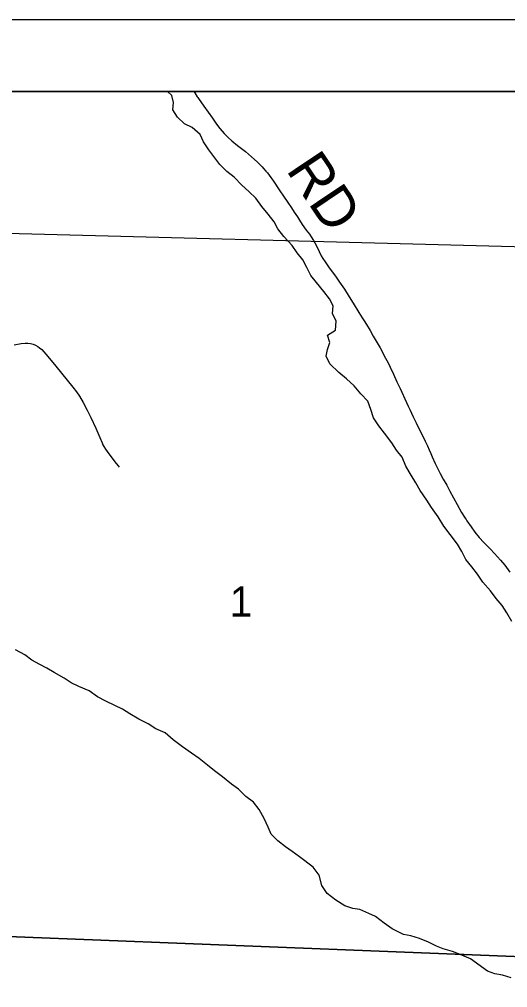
# Model space of a CAD drawing. Extents: x 0 to 34, y 0 to 22.
# Drawn here: x 26.316 to 26.994, y 19.658 to 21 of the extents above; entities that cross this region are included whole.
import ezdxf

# ---------------------------------------------------------------- set-up
doc = ezdxf.new("R2010")
doc.units = 0
for name, color, linetype in [('GM_X_Corporation', 7, 'Continuous'), ('GM_X_Minor_River', 7, 'Continuous'), ('GM_X_Section_Text', 7, 'Continuous'), ('GM_X_Township_Road', 7, 'Continuous'), ('GM_X_Township_Road_Text', 7, 'Continuous'), ('SH_Data', 7, 'Continuous')]:
    doc.layers.add(name, color=color, linetype=linetype)

msp = doc.modelspace()

# ---------------------------------------------------------------- linework, layer by layer
at = {"layer": 'GM_X_Corporation'}
for points in [[(30.3167, 20.9), (23.5167, 20.9), (23.5167, 14.7114), (24.6586, 14.6808), (24.6805, 14.6799), (26.0522, 14.6391), (26.4447, 14.6283), (26.4468, 14.6272), (26.4498, 14.6263), (26.4544, 14.6257), (26.5226, 14.6248), (26.5325, 14.6248), (26.5616, 14.6241), (26.5684, 14.624), (26.5727, 14.624), (26.5813, 14.6239), (26.5991, 14.6234), (26.6128, 14.6229), (26.6208, 14.6225), (26.6337, 14.622), (26.643, 14.6216), (26.6535, 14.621), (27.01, 14.6164)], [(30.3167, 20.9), (25.1014, 20.9), (25.0988, 20.7425), (25.0847, 19.8351), (25.0701, 18.7696), (25.0668, 18.5474), (25.0619, 17.7438), (25.4012, 17.7333), (26.0747, 17.7146), (26.0759, 17.6934), (26.0745, 17.4524), (26.0677, 16.948), (26.0646, 16.863), (26.0683, 16.6823), (26.3378, 16.673), (27.0694, 16.6556)]]:
    msp.add_lwpolyline(points, dxfattribs=at)
for points in [[(27.1148, 20.9), (26.1019, 20.9), (26.0969, 20.7089), (26.1216, 20.708), (27.1086, 20.6823)], [(26.1216, 20.708), (27.1086, 20.6823), (27.14, 20.6818), (27.1321, 19.6957), (26.1009, 19.7362)], [(27.1321, 19.6957), (27.1305, 19.6616), (27.1072, 18.6988), (26.0916, 18.7368), (26.1009, 19.7362)]]:
    msp.add_lwpolyline(points, close=True, dxfattribs=at)
at = {"layer": 'GM_X_Minor_River'}
for points in [[(26.9998, 20.1654), (26.9929, 20.1774), (26.986, 20.1872), (26.978, 20.197), (26.97, 20.2079), (26.9593, 20.2199), (26.952, 20.2308), (26.9443, 20.241), (26.9359, 20.2511), (26.9302, 20.2624), (26.9244, 20.2726), (26.9141, 20.2858), (26.9053, 20.2974), (26.8976, 20.3102), (26.888, 20.3234), (26.8819, 20.3332), (26.8723, 20.3467), (26.8662, 20.3576), (26.86, 20.3682), (26.8524, 20.3806), (26.8474, 20.3931), (26.8397, 20.4028), (26.8332, 20.413), (26.8229, 20.4265), (26.8152, 20.4363), (26.8079, 20.4476), (26.804, 20.4593), (26.7998, 20.4706), (26.7899, 20.4807), (26.7807, 20.492), (26.77, 20.5014), (26.7594, 20.5104), (26.7472, 20.5224), (26.7422, 20.5329), (26.744, 20.5424), (26.7473, 20.5519), (26.7438, 20.5621), (26.7551, 20.5691), (26.7557, 20.5816), (26.7507, 20.5921), (26.7517, 20.6028), (26.7467, 20.6126), (26.7387, 20.6227), (26.7288, 20.6351), (26.7207, 20.6449), (26.715, 20.6562), (26.7096, 20.6664), (26.7016, 20.6761), (26.6947, 20.6867), (26.6832, 20.6991), (26.6748, 20.7096), (26.6698, 20.7194), (26.6614, 20.7299), (26.6526, 20.7404), (26.6442, 20.7521), (26.6347, 20.7615), (26.6248, 20.7701), (26.6144, 20.7813), (26.6042, 20.7892), (26.5946, 20.799), (26.579, 20.8193), (26.5717, 20.8302), (26.567, 20.8404), (26.556, 20.8501), (26.5454, 20.8553), (26.5358, 20.8643), (26.5293, 20.8748), (26.53, 20.8847), (26.528, 20.8945), (26.5218, 20.9)], [(26.7048, 19.8387), (26.6949, 19.8461), (26.6854, 19.8529), (26.6751, 19.8611), (26.6656, 19.8701), (26.6614, 19.8799), (26.656, 19.8919), (26.6491, 19.9044), (26.641, 19.9149), (26.6307, 19.9224), (26.6205, 19.9329), (26.6106, 19.9396), (26.5984, 19.9497), (26.5873, 19.9583), (26.5774, 19.9658), (26.5656, 19.9751), (26.555, 19.9826), (26.5428, 19.9915), (26.5295, 20.0013), (26.5185, 20.0106), (26.5059, 20.0165), (26.4949, 20.0233), (26.482, 20.0299), (26.4698, 20.037), (26.4596, 20.0437), (26.4489, 20.0489), (26.4364, 20.0545), (26.4246, 20.0608), (26.4132, 20.069), (26.3988, 20.0749), (26.3882, 20.0801), (26.3787, 20.0868), (26.3646, 20.0946), (26.3544, 20.1006), (26.3449, 20.1054), (26.3335, 20.1117), (26.324, 20.1188), (26.3111, 20.1259)], [(26.9989, 19.6713), (26.9867, 19.6749), (26.9758, 19.6767), (26.9659, 19.6804), (26.9423, 19.6976), (26.9279, 19.7035), (26.9173, 19.7075), (26.9044, 19.7112), (26.8949, 19.7152), (26.8839, 19.7208), (26.8714, 19.7256), (26.8596, 19.7293), (26.8494, 19.7314), (26.8335, 19.7392), (26.8224, 19.7471), (26.8106, 19.7564), (26.8011, 19.7605), (26.7886, 19.766), (26.7788, 19.7674), (26.7678, 19.7711), (26.7556, 19.7786), (26.7434, 19.7879), (26.7362, 19.7992), (26.7323, 19.8136), (26.7238, 19.8245), (26.7048, 19.8387)]]:
    msp.add_lwpolyline(points, dxfattribs=at)
at = {"layer": 'GM_X_Township_Road'}
for points in [[(26.5584, 20.9), (26.5596, 20.898), (26.5632, 20.8925), (26.5638, 20.8916), (26.5649, 20.8902), (26.5723, 20.8797), (26.5785, 20.8712), (26.5841, 20.863), (26.5897, 20.8549), (26.5947, 20.8485), (26.6004, 20.8419), (26.606, 20.8361), (26.6111, 20.8316), (26.6192, 20.8249), (26.6299, 20.8166), (26.6384, 20.8095), (26.6461, 20.8024), (26.6531, 20.7954), (26.6552, 20.7931), (26.6585, 20.7894), (26.6605, 20.787), (26.6628, 20.7841), (26.6688, 20.7755), (26.6778, 20.7621), (26.6826, 20.7549), (26.6886, 20.7462), (26.6939, 20.7386), (26.6978, 20.7327), (26.702, 20.726), (26.7049, 20.7217), (26.7088, 20.7156), (26.7144, 20.7079), (26.7187, 20.702), (26.7211, 20.6986), (26.7244, 20.6935), (26.728, 20.6871), (26.7323, 20.6782), (26.7352, 20.6722), (26.7374, 20.6684), (26.7404, 20.6638), (26.7453, 20.6567), (26.7505, 20.6498), (26.755, 20.6439), (26.7607, 20.6357), (26.7673, 20.6259), (26.7739, 20.6155), (26.7795, 20.6065), (26.7874, 20.5938), (26.7919, 20.5864), (26.7945, 20.5822), (26.7978, 20.5769), (26.803, 20.5685), (26.8073, 20.561), (26.8167, 20.5445), (26.8245, 20.5305), (26.8279, 20.524), (26.8309, 20.518), (26.8356, 20.5081), (26.8402, 20.4975), (26.8419, 20.4937), (26.8445, 20.4881), (26.8469, 20.483), (26.851, 20.474), (26.8557, 20.4639), (26.8584, 20.4583), (26.8605, 20.4538), (26.8628, 20.4488), (26.8668, 20.4405), (26.8715, 20.4311), (26.8765, 20.4211), (26.8795, 20.4151), (26.8824, 20.4089), (26.8849, 20.4032), (26.8871, 20.3981), (26.889, 20.3937), (26.8932, 20.3844), (26.8958, 20.3789), (26.9003, 20.3702), (26.9045, 20.3627), (26.9093, 20.354), (26.9137, 20.3458), (26.9238, 20.3272), (26.9299, 20.3165), (26.9341, 20.3098), (26.935, 20.3083), (26.9361, 20.3068), (26.9373, 20.3048), (26.9431, 20.2962), (26.9482, 20.2892), (26.9545, 20.2815), (26.9608, 20.2745), (26.9695, 20.2657), (26.9756, 20.2595), (26.9838, 20.2503), (26.9898, 20.2431), (26.9969, 20.2337)], [(26.3089, 20.5488), (26.3187, 20.5505), (26.3243, 20.551), (26.328, 20.5509), (26.3317, 20.5505), (26.3353, 20.5495), (26.3387, 20.5481), (26.342, 20.5463), (26.3445, 20.5445), (26.3473, 20.5421), (26.3503, 20.5389), (26.3532, 20.5357), (26.356, 20.5324), (26.3671, 20.519), (26.3907, 20.4902), (26.3956, 20.4838), (26.3997, 20.4776), (26.4047, 20.469), (26.4105, 20.4581), (26.4155, 20.4481), (26.4223, 20.4334), (26.428, 20.4203), (26.431, 20.4128), (26.4323, 20.41), (26.4335, 20.4079), (26.4358, 20.4042), (26.4406, 20.3977), (26.4505, 20.3842), (26.4533, 20.3809), (26.455, 20.3791)]]:
    msp.add_lwpolyline(points, dxfattribs=at)
at = {"layer": 'SH_Data'}
for points in [[(23.4167, 21), (30.4167, 21), (30.4167, 14), (23.4167, 14)], [(23.5167, 20.9), (30.3167, 20.9), (30.3167, 14.1), (23.5167, 14.1)]]:
    msp.add_lwpolyline(points, close=True, dxfattribs=at)

# ---------------------------------------------------------------- texts
at = {"layer": 'GM_X_Section_Text'}
msp.add_text('1', height=0.0419, rotation=0, dxfattribs=at).set_placement((26.6082, 20.1719))
at = {"layer": 'GM_X_Township_Road_Text'}
msp.add_text('RD', height=0.05682, rotation=303.8274, dxfattribs=at).set_placement((26.6856, 20.7913))

doc.saveas('drawing.dxf')
